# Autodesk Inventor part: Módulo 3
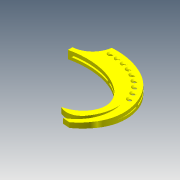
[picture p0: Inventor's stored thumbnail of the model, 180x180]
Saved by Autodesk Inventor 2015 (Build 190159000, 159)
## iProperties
Created: 2015-04
Part Number: Módulo 3
Material: Generic
Document SubType Name: Modeling
Designer: Gabriel Cabellos
Density: 1 g/cm^3
Appearance: Default
Author: Gabriel Cabellos
Sending System: SolidWorks 2008
Last Author: welington
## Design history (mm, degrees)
node "Módulo 31"
node "FurosModulo3"
node "Base1"
